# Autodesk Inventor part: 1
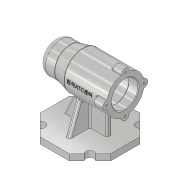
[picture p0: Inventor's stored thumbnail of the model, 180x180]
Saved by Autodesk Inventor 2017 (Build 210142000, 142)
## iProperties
Created: 2019-12
Part Number: 1
Material: 알루미늄 6061-AHC
Document SubType Name: Modeling
Designer: 5-13-le-1
Density: 2.7 g/cm^3
Appearance: 알루미늄 - 짙음
Mass: 725.066 g
Surface Area: 722.161 cm^2
Volume: 268.543 cm^3
Author: 5-13-le-1
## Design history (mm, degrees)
sketch "스케치2"
  geometry: L1 (56, -23.196)-(23.196, -56); L2 (23.196, -56)-(-23.196, -56); L3 (-23.196, -56)-(-56, -23.196); L4 (-56, -23.196)-(-56, 23.196); L5 (-56, 23.196)-(-23.196, 56); L6 (-23.196, 56)-(23.196, 56); L7 (23.196, 56)-(56, 23.196); L8 (56, 23.196)-(56, -23.196); C1 r 56 at (0, 0); 2 further points
  constraints: 16 end point, 2 coincident, 1 centre point, 1 vertical alignment, 17 other
  dimensions: "d0" = 112 diameter of C1; "d1" = 56 distance from line of L2 point (0, 0)
extrude "돌출1" new body sketch "스케치2" distance "d2" = 10; taper "d3" = 0 deg
sketch "스케치3"
  geometry: L1 (0, 0)-(-39.598, -39.598); L2 (0, 0)-(0, -29.306); L3 (0, 0)-(39.598, -39.598); C1 r 7.689 at (-39.598, -39.598); C2 r 6.56 at (39.598, -39.598); A1 r 56 centre (0, 0) between (-39.598, -39.598) and (39.598, -39.598); 1 further point
  constraints: 6 end point, 3 centre point, 2 point on circle, 1 coincident, 1 vertical
  dimensions: "d4" = 112 diameter of A1; "d5" = 45 deg angle of L2 L1; "d6" = 45 deg angle of L2 L3
extrude "돌출2" cut sketch "스케치3" stored distance "d7" = 10; taper "d8" = 0 deg
sketch "스케치4"
  geometry: L1 (-66.415, 80)-(56, 80); L2 (56, 80)-(56, 110); L3 (56, 110)-(-11, 110); L4 (-11, 110)-(-31, 105); L5 (-31, 105)-(-56, 105); L6 (-56, 105)-(-56, 80); L7 (41, 101)-(41, 104); L8 (41, 104)-(-13, 104); L9 (-13, 104)-(-13, 101); L10 (-13, 101)-(-25, 101); L11 (-25, 101)-(-25, 97.5); L12 (-25, 97.5)-(-43, 97.5); L13 (-43, 97.5)-(-43, 94.5); L14 (23.196, 0)-(34.959, 0) reference; L15 (-43, 97.5)-(-43, 96); L16 (-43, 96)-(-47, 96); L17 (-47, 96)-(-47, 90.5); L18 (-47, 90.5)-(-50, 90.5); L19 (-50, 90.5)-(-50, 80); L20 (41, 101)-(56, 101); 2 further points
  constraints: 38 end point, 10 perpendicular, 4 horizontal, 3 point on line, 1 midpoint, 1 parallel, 1 vertical, 1 vertical alignment
  dimensions: "d9" = 112 distance between parallel lines of L2 L6; "d10" = 25 distance of L4.end L5.end; "d11" = 45 distance from line of L3.end L6; "d13" = 54 distance of L7.end L8.end; "d14" = 12 distance of L9.end L10.end; "d15" = 18 distance of L11.end L12.end; "d18" = 60 diameter of L3 L1; "d19" = 80 distance between parallel lines of L14 L1; "d20" = 4 distance of L15.end L16.end; "d21" = 3 distance of L17.end L18.end; "d22" = 50 diameter of L5 L1; "d23" = 42 diameter of L20 L1; "d24" = 48 diameter of L8 L1; "d25" = 42 diameter of L10 L1; "d26" = 35 diameter of L12 L1; "d27" = 32 diameter of L16 L1; "d28" = 21 diameter of L18 L1; "d72" = 15 distance of L7.start L20.end
revolve "회전1" sketch "스케치4" stored, may be unused: angle "d29" = 90 deg
sketch "스케치5"
  geometry: L1 (10.05, -36)-(56.399, -19.13); L2 (10.05, 36)-(56.399, 19.13); L3 (10.05, 36)-(10.05, -36); L4 (10, -31.909)-(10, -45.035) reference; L5 (0, -56)-(10, -56) reference; L6 (0, 56)-(10, 56) reference; L7 (10, 45.035)-(10, 31.909) reference; L8 (56.399, 19.13)-(56.399, 18.521); L9 (56.399, -18.521)-(56.399, -19.13); C1 r 24 at (80, 0) reference; A1 r 30 centre (80, 0) between (56.399, 18.521) and (56.399, -18.521); 3 further points
  constraints: 10 end point, 2 point on circle, 2 vertical, 1 centre point, 1 coincident, 1 parallel
  dimensions: "d30" = 20 distance from line of L5 L1.start; "d31" = 20 distance from line of L2.start L6; "d32" = 110 deg angle of L4 L1; "d33" = 110 deg angle of L7 L2
extrude "돌출3" join sketch "스케치5" stored distance "d34" = 8; taper "d35" = 0 deg
sketch "스케치6"
  geometry: L1 (-45.035, 10)-(-31.909, 10) reference; L2 (-38, 10)-(-17.297, 54.398); L3 (-17.297, 54.398)-(31, 54.398); L4 (31, 54.398)-(31, 10); L5 (33.038, 10)-(44.237, 10) reference; L6 (-38, 10)-(31, 10); L7 (56, 0)-(56, 10) reference; L8 (-56, 0)-(-56, 10) reference; 3 further points
  constraints: 8 end point, 1 horizontal, 1 parallel, 1 perpendicular, 1 point on line
  dimensions: "d36" = 25 distance between parallel lines of L7 L4; "d37" = 18 distance from line of L2.start L8; "d38" = 115 deg angle of L1 L2
extrude "돌출4" join sketch "스케치6" stored distance "d39" = 8; taper "d40" = 0 deg
sketch "스케치7"
  geometry: L1 (0, 0)-(0, 30); C1 r 21 at (0, 0) reference; C2 r 6 at (0, 30); 2 further points
  constraints: 2 end point, 1 centre point, 1 coincident, 1 vertical, 1 vertical alignment, 1 other
  dimensions: "d41" = 12 diameter of C2
extrude "돌출5" join sketch "스케치7" distance "d42" = 16; taper "d43" = 0 deg
sketch "스케치8"
  geometry: A1 r 6 centre (0, 0) between (5.97, -0.6) and (-5.97, -0.6) reference; A2 r 6 centre (-30, -30) between (-29.4, -24.03) and (-29.4, -35.97) reference; A3 r 6 centre (0, -60) between (-5.97, -59.4) and (5.97, -59.4) reference; A4 r 6 centre (30, -30) between (29.4, -35.97) and (29.4, -24.03) reference; 5 further points
  constraints: 4 coincident
hole "구멍1" sketch "스케치8" at (0, 0), (-30, -30), (0, -60), (30, -30) diameter "d47" = 3.242; stored, may be unused: countersink angle "d51" = 90 deg, drill point angle "d53" = 118 deg; dims "d48" = 8, "d49" = 4, "d50" = 2, "d52" = 11
node "작업 평면1"
fillet "모깎기1" dims "d59" = 10
chamfer "모따기1" distance "d61" = 1; stored, may be unused: second distance "d62" = 2, angle "d63" = 45 deg
fillet "모깎기3" dims "d64" = 3
fillet "모깎기4" dims "d65" = 3
fillet "모깎기5" dims "d66" = 0.3
fillet "모깎기8" dims "d69" = 3
fillet "모깎기11" dims "d73" = 3
fillet "모깎기12" dims "d74" = 3
fillet "모깎기13" dims "d75" = 3
fillet "모깎기14" dims "d76" = 1
fillet "모깎기15" dims "d77" = 3
fillet "모깎기16" dims "d78" = 1
fillet "모깎기17" dims "d79" = 3
sketch "스케치10"
  geometry: L1 (45.75, 79.454)-(-18.778, 79.454); L2 (56, 86.771)-(56, 109.226) reference; 1 further point
  constraints: 2 end point, 2 horizontal
  dimensions: "d80" = 10.25 distance from line of L2 L1.start
feature "엠보싱2" sketch "스케치10" dims "d81" = 0.5, "d82" = 0
node "솔리드1"
mirror "미러1"
pattern_circular "원형 패턴1" dims angle "d45" = 360 deg
